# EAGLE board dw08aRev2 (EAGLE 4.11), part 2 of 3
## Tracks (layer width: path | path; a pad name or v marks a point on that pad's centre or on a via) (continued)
I_ACCEPT  (via drill 0.61) (continued)
  Bottom 0.152: v151.38,13.21 154.94,13.21 172.21,30.48 173.61,30.48 184.28,41.15 184.28,42.16 v198.75,56.64 | B07.S2 224.28,21.34 225.93,22.99 225.93,24.38 226.95,25.4 v227.33,25.4 227.71,25.65 227.97,25.91 230.76,25.91 231.52,26.67 v233.93,26.67 | v249.17,11.68 v258.95,21.46 | v232.28,63.25 232.41,63.37 233.55,63.37 235.46,65.28 235.46,65.66 236.6,66.8 236.6,67.06 259.59,90.04 261.24,90.04 A04.S2 | v238.51,56.9 238.51,52.2 228.09,41.78 228.09,41.27 v221.11,34.29
I_ACCLR  (via drill 0.61)
  Top 0.152: v297.94,54.36 297.94,56.13 297.43,56.64 297.05,56.64 296.55,57.15 296.55,57.66 v285.12,69.09 | v292.48,78.11 292.48,80.64 278.38,94.74 276.99,94.74 275.34,96.39 A03.P2 | v124.71,2.41 84.71,42.42 81.66,42.42 B18.J2 | v187.83,15.88 188.98,15.88 191.01,13.84 191.01,13.72 194.69,10.03 v203.58,10.03 | v214,15.88 214.25,15.88 v228.09,2.03 | v242.95,12.7 242.95,12.57 245.49,10.03 247.27,10.03 v250.57,6.73
  Bottom 0.152: v297.94,54.36 250.44,6.86 v250.57,6.73 251.33,5.97 252.22,5.97 256.29,10.03 259.33,10.03 267.21,17.91 267.21,21.21 272.54,26.54 273.94,26.54 B03.P2 | v285.12,69.09 285.12,70.74 v292.48,78.11 | v124.71,2.41 129.92,2.41 131.57,0.76 168.53,0.76 170.31,2.54 171.58,2.54 172.47,3.43 172.72,3.43 173.48,4.19 173.99,4.19 185.17,15.37 187.32,15.37 v187.83,15.88 | v203.58,10.03 204.72,10.03 207.26,12.57 208.41,12.57 208.79,12.95 211.46,12.95 212.22,13.72 212.22,14.1 v214,15.88 | v228.09,2.03 229.49,2.03 230.63,3.17 233.43,3.17 v242.95,12.7
I_ADD00  (via drill 0.61)
  Top 0.152: v62.61,51.31 58.8,55.12 56.26,55.12 B20.D2 | v108.58,92.46 112.27,92.46 115.32,89.41 119.13,89.41 v163.7,44.83 | v197.61,76.2 197.61,76.07 204.09,69.6 204.98,69.6 210.57,64.01 214.63,64.01 v216.41,62.23 | v240.92,59.31 239.78,60.45 239.01,60.45 228.22,71.25 v228.22,71.88 227.97,72.26 v225.04,75.18 | v253.49,71.88 261.37,64.01 262.76,64.01 264.41,62.36 B04.B1 | v272.92,123.06 271.65,124.33 270.89,124.33 265.56,129.67 265.56,131.06 A04.B1
  Bottom 0.152: v62.61,51.31 67.44,51.31 v108.58,92.46 | v163.7,44.83 163.83,44.83 185.17,66.17 185.67,66.17 190.75,71.25 192.66,71.25 v197.61,76.2 | v216.41,62.23 218.57,62.23 v228.22,71.88 | v240.92,59.31 v253.49,71.88 | v272.92,123.06 272.8,123.06 241.3,91.57 240.79,91.57 232.41,83.19 232.41,82.55 v225.04,75.18
I_ADD01  (via drill 0.61)
  Top 0.152: v81.66,27.3 60.2,48.77 56.26,48.77 B20.F2 | v190.5,119.63 192.53,119.63 204.09,108.08 209.04,108.08 228.6,88.52 230,88.52 232.66,85.85 233.17,85.85 235.2,83.82 | 235.2,83.82 261.37,57.66 262.76,57.66 264.41,56.01 B04.D1 | v269.37,118.24 265.56,122.05 265.56,124.71 A04.D1 | 235.2,83.82 v234.95,83.57
  Bottom 0.152: v81.66,27.3 82.8,27.3 89.92,34.42 101.6,34.42 149.99,82.8 150.5,82.8 165.99,98.3 166.5,98.3 169.29,101.09 173.35,101.09 178.69,106.43 178.69,106.68 185.42,113.41 185.42,113.92 186.82,115.32 186.82,115.95 187.96,117.09 188.59,117.09 189.99,118.49 189.99,119.13 v190.5,119.63 | v269.37,118.24 269.37,115.32 265.68,111.63 264.29,111.63 264.03,111.38 262.13,111.38 235.46,84.71 235.46,84.07 v234.95,83.57
I_ADD02  (via drill 0.61)
  Top 0.152: v108.71,80.9 108.84,80.9 116.46,73.28 117.09,73.28 125.73,64.64 126.62,64.64 v139.95,51.31 | v220.09,128.91 220.98,128.91 233.17,116.71 233.17,116.46 v246.63,103 | v266.83,55.37 267.84,54.36 267.84,53.09 B04.E1 | v268.48,60.33 268.48,61.21 260.6,69.09 260.22,69.09 250.44,78.87 249.81,78.87 243.46,85.22 243.21,85.22 v242.32,86.11 | v248.92,105.16 v255.14,98.93
  Bottom 0.152: v108.71,80.9 105.54,77.72 103.38,77.72 102.74,77.09 100.33,77.09 67.18,43.94 61.34,43.94 60.71,43.31 56.26,43.31 B20.J2 | v139.95,51.31 141.86,51.31 155.07,64.52 155.07,67.69 155.19,67.82 155.19,68.33 183.26,96.39 183.64,96.39 188.34,101.09 192.28,101.09 v220.09,128.91 | v246.63,103 246.89,103 249.05,105.16 | 249.05,105.16 264.41,120.52 266.32,120.52 267.59,121.79 A04.E1 | v266.83,55.37 266.83,58.93 267.72,59.82 267.97,59.82 v268.48,60.33 | v255.14,98.93 v242.32,86.11 | 249.05,105.16 v248.92,105.16
I_ADD03  (via drill 0.61)
  Top 0.152: v65.02,29.08 58.04,36.07 56.26,36.07 B20.L2 | v81.28,32.13 81.53,32.13 v91.57,22.1 | v202.82,116.46 202.82,116.2 210.57,108.46 214.38,108.46 220.85,101.98 221.62,101.98 222.38,101.22 222.88,101.22 223.77,100.33 224.54,100.33 239.65,85.22 240.28,85.22 242.32,87.25 | 242.32,87.25 248.67,80.9 249.3,80.9 268.86,61.34 268.86,61.09 269.24,60.71 269.24,59.44 v274.7,53.98 | v266.19,117.6 267.46,116.33 267.59,116.33 A04.H1 | v245.62,97.03 245.62,95.76 v248.16,93.22 | 242.32,87.25 v242.19,87.38
  Bottom 0.152: v65.02,29.08 78.23,29.08 v81.28,32.13 | v91.57,22.1 107.7,22.1 121.28,35.69 121.67,35.69 141.73,55.75 142.11,55.75 v202.82,116.46 | v274.7,53.98 274.57,53.98 270.38,49.78 270.38,48.77 268.35,46.74 B04.H1 | v266.19,117.6 266.19,116.97 254.51,105.28 254,105.28 245.75,97.03 v245.62,97.03 | v248.16,93.22 248.03,93.22 v242.19,87.38
I_ADD04  (via drill 0.61)
  Top 0.152: v126.75,78.74 129.29,78.74 158.24,49.78 158.24,45.85 v159.13,44.96 | v196.85,77.72 200.91,77.72 v213.11,65.53 | v263.65,44.2 264.41,43.43 264.41,43.31 B04.J1 | v266.32,47.5 266.32,49.66 v233.17,82.8
  Bottom 0.152: v126.75,78.74 79.25,31.24 61.34,31.24 60.71,30.61 56.26,30.61 B20.N2 | v159.13,44.96 160.91,44.96 161.42,45.47 162.05,45.47 189.61,73.03 189.61,73.66 193.17,77.22 196.34,77.22 v196.85,77.72 | v213.11,65.53 215.77,65.53 224.66,74.42 225.43,74.42 225.81,74.8 225.81,75.44 v233.17,82.8 234.19,83.82 234.19,83.95 262,111.76 263.91,111.76 264.41,112.27 A04.J1 | v263.65,44.2 263.65,44.83 v266.32,47.5
I_ADD05  (via drill 0.61)
  Top 0.152: v106.93,21.34 107.19,21.34 v123.83,4.7 | v170.56,34.42 175.77,34.42 v198.37,11.81 | v202.06,15.49 202.06,14.86 208.03,8.89 208.79,8.89 v215.52,2.16 | v237.87,15.49 v234.95,15.49 | v262.89,38.23 263.14,38.23 264.41,36.96 B04.L1 | v264.03,109.09 264.67,108.46 264.67,107.06 A04.L1 | v275.08,120.52 274.45,120.52 272.67,122.3 272.42,122.3 v258.19,136.53 | v256.16,136.53 253.37,139.32 248.41,139.32 v247.9,139.83 | v147.07,43.81 147.7,43.81 v162.94,28.57
  Bottom 0.152: v106.93,21.34 104.14,18.54 99.44,18.54 90.55,9.65 58.8,9.65 57.02,7.87 54.48,10.41 54.48,11.68 58.8,16 56.01,18.8 56.01,23.11 B20.R2 | v123.83,4.7 136.4,4.7 159.77,28.07 162.94,28.07 | 162.94,28.07 164.21,28.07 v170.56,34.42 | v202.06,15.49 v198.37,11.81 | v215.52,2.16 216.66,3.3 217.04,3.3 226.31,12.57 229.36,12.57 229.74,12.95 232.41,12.95 v234.95,15.49 | v237.87,15.49 240.16,15.49 v262.89,38.23 | v264.03,109.09 264.03,109.47 v275.08,120.52 | v256.16,136.53 v258.19,136.53 | v247.9,139.83 246.89,138.81 246.25,138.81 245.36,137.92 242.32,137.92 238.89,134.49 238.25,134.49 219.71,115.95 219.2,115.95 167.26,64.01 167,64.01 166.5,63.5 166.5,63.25 v147.07,43.81 | 162.94,28.07 v162.94,28.57
I_ADD06  (via drill 0.61)
  Top 0.152: v145.92,143.26 176.15,143.26 v178.82,140.59 | v195.07,142.88 211.46,142.88 212.34,141.99 213.23,141.99 v221.36,133.86 | v226.31,133.86 229.11,133.86 v233.93,129.03 | v252.09,142.88 252.09,142.24 257.3,137.03 257.3,136.27 257.81,135.76 258.44,135.76 272.29,121.92 272.54,121.92 v279.53,114.94 | v271.14,32.89 268.99,32.89 B04.M1 | v276.1,37.85 276.1,41.15 v273.56,43.69 | v295.91,70.1 295.91,70.61 287.78,78.74 287.78,79.38 280.67,86.49 280.67,87.63 275.21,93.09 275.21,94.61 270.38,99.44 270.38,100.84 268.73,102.49 A04.M1
  Bottom 0.152: v145.92,143.26 69.72,67.06 68.58,67.06 68.33,66.8 64.39,66.8 63.75,66.17 58.17,66.17 52.45,60.45 51.69,60.45 49.78,58.55 48.51,58.55 45.97,56.01 43.56,56.01 B21.D2 | v178.82,140.59 189.99,140.59 191.39,139.19 v195.07,142.88 | v221.36,133.86 v226.31,133.86 | v233.93,129.03 235.33,129.03 242.32,136.02 245.24,136.02 v252.09,142.88 | v279.53,114.94 279.53,112.78 272.03,105.28 270.64,105.28 268.99,103.63 A04.M1 | v276.1,37.85 v271.14,32.89 | v273.56,43.69 273.56,47.24 291.59,65.28 291.59,65.79 v295.91,70.1
I_ADD07  (via drill 0.61)
  Top 0.152: v266.83,28.32 267.59,27.56 267.59,27.43 B04.P1 | v273.3,36.2 273.3,37.59 v270.51,40.39 270.13,40.64 263.27,47.5 v259.59,47.5 | v291.97,67.31 291.97,69.34 282.45,78.87 282.45,80.52 279.53,83.44 279.53,83.95 276.73,86.74 276.73,87.25 275.08,88.9 274.57,88.9 270.38,93.09 270.38,94.49 268.73,96.14 A04.P1 | v129.92,120.52 133.86,120.52 147.19,107.19 148.34,107.19 150.24,105.28 155.83,105.28 188.47,72.64 193.8,72.64 v198.12,68.33 | v208.41,77.85 212.72,77.85 237.62,52.96 237.62,49.91 v237.74,49.78 | v235.59,43.43 235.59,42.29 237.62,40.26 237.62,39.62 238,39.24 240.03,39.24 v243.97,35.31
  Bottom 0.152: v266.83,28.32 266.83,29.72 v273.3,36.2 | v270.51,40.39 270.64,40.39 272.54,42.29 272.54,46.74 291.21,65.41 291.21,66.55 v291.97,67.31 | v129.92,120.52 100.97,91.57 96.27,91.57 64.52,59.82 58.17,59.82 55.63,57.28 54.86,57.28 53.98,56.39 52.07,56.39 45.34,49.66 43.56,49.66 B21.F2 | v198.12,68.33 199.52,68.33 201.55,70.36 201.55,70.99 v208.41,77.85 | v237.74,49.78 237.74,45.59 v235.59,43.43 | v243.97,35.31 247.4,35.31 v259.59,47.5
I_ADD08  (via drill 0.61)
  Top 0.152: v301.37,55.5 301.37,55.75 295.78,61.34 295.78,64.39 295.4,64.77 295.4,65.91 v295.02,66.29 | v299.85,72.64 299.85,74.3 293.5,80.64 293.5,81.28 v280.8,93.98 | v274.7,88.14 274.19,88.14 273.3,89.03 270,89.03 268.99,90.04 A04.S1 | v41.78,28.57 45.21,25.15 46.23,25.15 48.64,22.73 60.83,22.73 73.91,9.65 98.17,9.65 v102.74,5.08 | v163.07,14.35 164.97,14.35 169.29,10.03 172.47,10.03 179.71,2.79 v179.71,2.67 | v216.15,29.46 216.15,26.67 226.44,16.38 231.39,16.38 v243.46,4.32 | v260.35,20.32 260.6,20.32 264.54,16.38 265.68,16.38 268.61,19.3 267.97,19.94 B04.S1
  Bottom 0.152: v301.37,55.5 301.12,55.24 301.12,51.82 283.72,34.42 280.42,34.42 278.89,32.89 278.89,29.59 270.89,21.59 270.51,21.59 270,21.08 268.99,21.08 B04.S1 | v295.02,66.29 295.02,67.82 v299.85,72.64 | v280.8,93.98 280.54,93.98 v274.7,88.14 | v41.78,28.57 41.78,37.08 42.42,37.72 42.42,42.16 B21.J2 | v102.74,5.08 107.06,0.76 119.25,0.76 122.43,3.94 149.99,3.94 151,4.95 153.67,4.95 v163.07,14.35 | v179.71,2.67 188.47,2.67 196.34,10.54 196.34,10.92 197.99,12.57 198.37,12.57 199.52,13.72 199.52,14.1 201.68,16.26 203.07,16.26 213.49,26.67 213.49,26.8 v216.15,29.46 | v243.46,4.32 250.32,11.18 250.32,11.68 258.95,20.32 v260.35,20.32
I_ADD09  (via drill 0.61)
  Top 0.152: v157.23,140.84 v169.29,140.84 | v178.18,142.37 179.45,143.64 233.81,143.64 235.2,142.24 235.59,142.24 236.35,141.48 236.73,141.48 242.19,136.02 243.46,136.02 250.32,129.16 250.32,128.52 v251.84,127 | v281.69,77.09 283.08,77.09 v283.59,76.58 | v298.96,91.69 298.96,94.87 296.67,97.16 296.67,97.92 286.38,108.2 283.97,108.2 265.68,126.49 262.51,126.49 v262.38,126.62
  Bottom 0.152: v157.23,140.84 142.88,126.49 137.54,126.49 135.25,124.21 134.75,124.21 100.2,89.66 99.06,89.66 91.06,81.66 91.06,79.76 77.47,66.17 77.22,66.17 71.63,60.58 68.58,60.58 48.77,40.77 45.47,40.77 43.31,38.61 43.31,37.21 B21.L2 | v169.29,140.84 176.66,140.84 v178.18,142.37 | v251.84,127 256.92,127 258.06,125.86 A04.D2 259.46,125.86 260.22,126.62 v262.38,126.62 | v281.69,77.09 269.75,65.15 269.75,64.39 268.99,63.63 268.99,62.99 262,56.01 259.46,56.01 B04.D2 | v283.59,76.58 284.23,76.58 286.38,78.74 286.38,79.12 v298.96,91.69
I_ADD10  (via drill 0.61)
  Top 0.152: v101.22,7.75 98.93,10.03 74.04,10.03 59.05,25.02 48.51,25.02 48.01,25.53 45.34,25.53 43.31,27.56 43.31,29.46 B21.N2 | v142.49,38.1 144.53,38.1 v147.32,35.31 | v188.85,73.41 194.18,73.41 v196.22,71.37 | v204.6,76.33 216.92,64.01 221.23,64.01 231.78,53.47 232.03,53.47 v241.68,43.81 | v256.67,56.9 256.67,56.01 258.19,54.48 259.59,54.48 261.24,52.83 B04.E2 | v258.7,115.95 258.7,115.57 v272.54,101.73 | v260.99,86.87 260.99,86.74 266.19,81.53 266.19,79.88 v278,68.07
  Bottom 0.152: v101.22,7.75 106.43,7.75 107.06,8.38 107.82,8.38 118.36,18.92 123.32,18.92 v142.49,38.1 | v147.32,35.31 147.96,35.31 159.77,47.12 163.07,47.12 180.47,64.52 180.47,65.02 v188.85,73.41 | v196.22,71.37 198.37,71.37 198.75,71.75 200.03,71.75 v204.6,76.33 | v241.68,43.81 242.32,43.81 251.33,52.83 252.6,52.83 v256.67,56.9 | v258.7,115.95 261.49,118.75 261.49,121.54 A04.E2 | v272.54,101.73 272.54,97.79 262,87.25 261.37,87.25 v260.99,86.87 | v278,68.07 278,66.8 275.21,64.01 274.95,64.01 274.57,63.63 274.57,61.85 267.33,54.61 265.81,54.61 265.68,54.48 264.29,54.48 262.64,52.83 B04.E2
I_ADD11  (via drill 0.61)
  Top 0.152: v170.94,97.92 175.64,97.92 v184.15,89.41 | v239.01,141.1 239.9,141.1 254.76,126.24 254.76,124.71 259.84,119.63 259.84,118.24 261.49,116.59 A04.H2 | v222.76,50.04 v242.7,30.1 | v223.14,63.25 v228.98,57.4 | v219.07,61.59 218.19,61.59 213.49,66.29 212.85,66.29 200.53,78.61 198.12,78.61 197.74,78.99 192.53,78.99 189.48,82.04 185.04,82.04 v181.99,85.09
  Bottom 0.152: v170.94,97.92 166.12,97.92 150.62,82.42 150.11,82.42 92.58,24.89 80.39,24.89 72.64,17.14 71.25,18.54 61.34,18.54 60.2,17.4 57.66,19.94 57.66,21.21 58.8,22.35 56.26,24.89 48.64,24.89 48.01,24.26 43.56,24.26 B21.R2 | v184.15,89.41 186.31,89.41 | 186.31,89.41 191.77,94.87 193.8,94.87 202.18,103.25 202.18,103.89 204.09,105.79 204.09,106.17 220.47,122.56 220.6,122.56 239.01,140.97 v239.01,141.1 | v242.7,30.1 258.19,45.59 261.24,45.59 B04.H2 | v222.76,50.04 223.14,50.04 228.09,54.99 228.09,56.52 v228.98,57.4 | v223.14,63.25 220.34,63.25 219.58,62.48 219.58,62.1 v219.07,61.59 | 186.31,89.41 v181.99,85.09
I_BAC00  (via drill 0.61)
  Top 0.152: v195.83,34.29 186.18,43.94 186.18,45.34 B10.H2 | v224.41,63.25 225.43,63.25 226.31,62.36 B07.B1 | v275.97,93.47 281.05,88.39 281.05,86.61 v288.54,79.12 302.77,64.9 302.77,62.61 B01.B1 | v305.82,117.47 305.82,121.16 305.31,121.67 305.31,129.41 303.66,131.06 A01.B1 | v254.76,87.88 259.08,83.57 260.22,83.57 v276.23,67.56
  Bottom 0.152: v195.83,34.29 195.83,34.67 v224.41,63.25 | v275.97,93.47 275.97,93.98 283.46,101.47 283.97,101.47 286.77,104.27 291.08,104.27 294.39,107.57 295.91,107.57 v305.82,117.47 | v254.76,87.88 249.3,82.42 248.67,82.42 247.14,80.9 247.14,80.39 229.11,62.36 227.71,62.36 B07.B1 | v276.23,67.56 276.35,67.56 277.62,68.83 278.26,68.83 v288.54,79.12
I_BAC01  (via drill 0.61)
  Top 0.152: v185.42,30.23 186.18,30.23 v192.02,24.38 | v224.79,57.28 225.04,57.28 226.31,56.01 B07.D1 | v301.75,60.07 302.77,59.05 302.77,56.26 B01.D1 | v301.75,64.01 301.75,65.02 300.61,66.17 298.58,66.17 v285.62,79.12 285.24,79.38 v283.59,79.38 | v306.2,101.6 306.2,101.73 305.31,102.62 305.31,114.55 304.67,115.19 304.67,115.82 302.13,118.36 302.13,119.63 304.93,122.43 304.93,123.44 303.66,124.71 A01.D1 | v249.05,81.66 266.06,64.64 267.08,64.64 v268.22,63.5
  Bottom 0.152: v185.42,30.23 183.26,30.23 B10.N2 | v192.02,24.38 224.79,57.15 v224.79,57.28 225.04,57.66 v249.05,81.66 | v301.75,64.01 v301.75,60.07 | v285.62,79.12 285.88,79.12 294.13,87.38 294.13,88.01 300.99,94.87 300.99,95.5 303.15,97.66 303.4,97.66 305.82,100.08 305.82,101.22 v306.2,101.6 | v268.22,63.5 268.35,63.5 269.37,64.52 269.37,65.91 281.31,77.85 282.07,77.85 v283.59,79.38
I_BAC02  (via drill 0.61)
  Top 0.152: v184.28,16.64 185.29,15.62 185.29,14.99 B10.U2 | v222.25,55.75 223.39,55.75 v228.22,50.93 | v278.13,15.37 275.21,15.37 272.03,18.54 271.53,18.54 271.02,19.05 271.02,19.56 259.33,31.24 255.4,31.24 242.06,44.58 241.81,44.58 v232.16,54.23
  Bottom 0.152: v184.28,16.64 184.28,16.89 187.2,19.81 187.2,20.45 189.99,23.24 189.99,23.5 191.64,25.15 192.28,25.15 214.25,47.12 214.25,47.5 221.74,54.99 221.74,55.24 v222.25,55.75 | v228.22,50.93 228.47,50.93 229.49,51.94 B07.E1 232.03,54.23 v232.16,54.23 232.54,54.48 233.93,54.48 236.73,57.28 237.24,57.28 266.95,87 266.95,87.76 268.61,89.41 268.86,89.41 272.8,93.34 272.8,93.6 274.95,95.76 275.21,95.76 276.23,96.77 276.61,96.77 296.55,116.71 296.55,117.35 297.18,117.98 297.43,117.98 301.24,121.79 305.69,121.79 A01.E1 | v278.13,15.37 302.13,39.37 302.13,43.43 304.17,45.47 304.17,46.86 305.05,47.75 305.05,48.39 305.82,49.15 305.82,50.93 305.94,51.05 305.94,51.69 B01.E1
I_BAC03  (via drill 0.61)
  Top 0.152: v177.8,49.53 178.31,49.53 v206.63,21.21 | v222.63,36.96 v222.63,34.67 222.76,34.29 222.76,31.11 228.09,25.78 228.09,25.53 230.38,23.24 230.38,22.99 v235.59,17.78 | v296.16,65.15 299.72,61.59 299.72,60.96 302.13,58.55 302.13,54.99 v303.53,53.59 304.67,52.45 304.67,51.94 305.82,50.8 305.82,50.16 306.58,49.4 306.58,46.74 B01.H1 | v304.67,77.6 304.42,77.6 301.75,80.26 301.75,80.52 293.75,88.52 292.74,88.52 v289.05,92.2 | v244.35,24.51 244.35,23.88 245.49,22.73 249.43,22.73 253.24,18.92 255.52,18.92 v260.22,14.22 | v282.07,35.18 v283.59,33.66
  Bottom 0.152: v177.8,49.53 177.29,49.02 177.29,48.64 175.13,46.48 173.74,46.48 B11.H2 | v206.63,21.21 207.01,21.21 215.39,29.59 215.39,30.99 216.41,32 219.96,32 v222.63,34.67 | v222.63,36.96 222.76,36.96 228.09,42.29 228.09,43.69 229.74,45.34 B07.H1 | v296.16,65.15 301.75,70.74 301.75,74.68 v304.67,77.6 | v289.05,92.2 289.05,96.14 295.4,102.49 295.4,103.25 304.29,112.14 304.29,113.54 305.94,115.19 A01.H1 | v235.59,17.78 237.62,17.78 v244.35,24.51 | v260.22,14.22 260.22,14.73 280.29,34.8 281.69,34.8 v282.07,35.18 | v283.59,33.66 v303.53,53.59
I_BAC04  (via drill 0.61)
  Top 0.152: v186.82,16.89 173.74,29.97 170.56,29.97 B11.N2 | v205.1,35.69 206.5,35.69 v212.47,29.72 | v305.82,48.01 305.82,49.02 v297.31,57.53 | v300.48,61.34 300.48,61.98 295.4,67.06 294.77,67.06 282.83,78.99 282.83,80.64 279.91,83.57 279.91,87.25 v279.65,87.5 | v228.85,41.4 227.84,42.42 227.71,42.42 B07.J1 | v270.38,83.57 270.51,83.57 v273.05,81.03
  Bottom 0.152: v186.82,16.89 186.82,17.53 193.17,23.88 193.17,24.51 199.26,30.61 200.03,30.61 v205.1,35.69 | v212.47,29.72 212.47,29.97 223.27,40.77 224.66,40.77 226.31,42.42 B07.J1 | v305.82,48.01 304.55,46.74 304.55,45.34 303.66,44.45 303.66,43.56 B01.J1 | v297.31,57.53 297.31,58.17 v300.48,61.34 | A01.J1 302.51,112.27 300.86,110.62 299.47,110.62 295.53,106.68 295.53,106.43 293.37,104.27 293.12,104.27 279.65,90.81 v279.65,87.5 279.4,87.12 273.3,81.03 v273.05,81.03 | v228.85,41.4 228.85,42.04 237.36,50.55 238,50.55 261.37,73.91 261.37,74.55 v270.38,83.57
I_BAC05  (via drill 0.61)
  Top 0.152: v205.87,55.12 206.76,55.12 210.57,51.31 213.87,51.31 215.39,49.78 215.39,46.48 216.92,44.96 217.17,44.96 217.93,44.2 217.93,43.43 219.96,41.4 220.47,41.4 v224.92,36.96 | v280.04,16.13 277.5,16.13 276.73,16.89 276.73,21.97 260.22,38.48 259.08,38.48 v251.46,46.1 | v236.47,30.48 235.2,30.48 233.93,31.75 233.43,31.75 230.76,34.42 229.36,34.42 227.71,36.07 B07.L1 | v299.59,104.78 300.1,104.78 304.29,100.58 304.29,100.08 304.67,99.69 304.93,99.69 v306.2,98.42 | v289.81,73.79 290.32,73.79 291.97,72.14 291.97,71.5 302.64,60.83 303.28,60.83 304.67,59.44 304.67,52.96 305.05,52.58 305.05,52.07 v306.58,50.55
  Bottom 0.152: v205.87,55.12 186.82,36.07 186.82,32.77 186.18,32.13 186.18,29.84 173.48,17.14 173.48,14.99 B11.U2 | v224.92,36.96 226.31,36.96 B07.L1 | v280.04,16.13 299.97,36.07 302.51,36.07 B01.L1 303.66,37.21 305.31,38.86 305.31,46.61 305.94,47.24 306.2,47.24 306.58,47.62 v306.58,50.55 | v251.46,46.1 251.46,45.47 v236.47,30.48 | v299.59,104.78 300.74,105.92 302.51,105.92 A01.L1 | v306.2,98.42 306.2,98.3 302.13,94.23 302.13,91.31 301.88,91.06 301.88,90.42 297.05,85.6 297.05,83.31 296.67,82.93 296.67,82.42 295.78,81.53 295.78,79.76 v289.81,73.79
I_BAC06  (via drill 0.61)
  Top 0.152: 237.24,27.94 240.79,24.38 240.79,21.59 241.55,20.83 241.55,20.32 245.49,16.38 250.32,16.38 255.52,11.18 257.05,11.18 258.19,10.03 259.59,10.03 v264.29,5.33 | 237.24,27.94 233.81,31.37 233.3,31.37 231.78,32.89 230.89,32.89 B07.M1 | v189.99,71.63 193.68,71.63 197.74,67.56 200.03,67.56 202.82,64.77 203.07,64.77 207.39,60.45 207.39,59.94 222.63,44.7 222.63,44.45 229.74,37.34 230.38,37.34 233.3,34.42 233.68,34.42 237.24,30.86 237.24,27.94 | v162.05,44.32 B12.H2 | v280.8,73.79 280.8,69.72 302.51,48.01 302.51,45.21 304.29,43.43 304.29,35.69 305.94,34.04 B01.M1
  Bottom 0.152: v264.29,5.33 292.74,5.33 297.94,10.54 297.94,16.89 301.12,20.07 301.12,25.91 304.8,29.59 304.8,31.5 305.94,32.64 B01.M1 | v162.05,44.32 163.32,45.59 163.96,45.59 v189.99,71.63 | v280.8,73.79 282.83,75.82 282.83,76.96 284.86,78.99 284.86,79.5 286.13,80.77 284.99,81.92 284.99,84.07 297.31,96.39 297.94,96.39 304.29,102.74 305.69,102.74 A01.M1
I_BAC07  (via drill 0.61)
  Top 0.152: v263.65,4.19 261.75,6.1 256.29,6.1 255.91,6.48 252.73,6.48 236.98,22.23 236.98,22.61 234.06,25.53 233.3,25.53 232.28,26.54 230.89,26.54 B07.P1 229.74,27.69 228.09,29.34 228.09,30.73 227.58,31.24 v225.81,31.24 | v186.18,8.76 185.29,9.65 181.86,9.65 179.96,11.56 179.58,11.56 170.43,20.7 169.16,20.7 161.16,28.7 160.4,28.7 159.38,29.72 157.86,29.72 B12.N2 | v211.84,17.4 v205.49,23.75 | v304.42,84.96 v304.42,94.87 | v303.66,59.31 v291.21,71.75 | v292.23,47.5 292.23,42.8 304.29,30.73 304.29,29.34 305.94,27.69 B01.P1
  Bottom 0.152: v263.65,4.19 292.1,4.19 298.32,10.41 298.32,16.76 301.5,19.94 301.5,20.45 304.29,23.24 304.29,24.64 305.94,26.29 B01.P1 | v186.18,8.76 190.5,8.76 v205.49,23.75 | v211.84,17.4 211.96,17.4 v225.81,31.24 | v291.21,71.75 v304.42,84.96 | v303.66,59.31 303.66,58.93 v292.23,47.5 | v304.42,94.87 A01.P1
I_BAC08  (via drill 0.61)
  Top 0.152: v175.26,4.32 174.75,4.83 170.94,4.83 165.74,10.03 162.94,10.03 160.78,12.19 160.78,13.59 B12.U2 | v194.56,20.7 199.9,15.37 200.53,15.37 208.66,7.24 208.66,6.6 v209.3,5.97 | v227.71,22.1 228.47,22.1 229.49,21.08 B07.S1 | v232.16,22.35 248.28,6.22 248.54,6.22 249.81,4.95 257.94,4.95 260.6,2.29 262.76,2.29 263.02,2.03 266.7,5.71 266.7,7.75 266.57,7.87 270.89,12.19 278.51,12.19 289.05,1.65 305.94,18.54 305.94,19.94 B01.S1 305.94,21.34 304.29,22.99 304.29,24.38 296.55,32.13 v296.55,34.92 | v293.62,75.31 293.62,74.55 v305.44,62.74
  Bottom 0.152: v175.26,4.32 178.18,4.32 v194.56,20.7 | v209.3,5.97 211.58,5.97 v227.71,22.1 | v232.16,22.35 230.89,21.08 B07.S1 | v293.62,75.31 305.94,87.63 305.94,89.79 A01.S1 | v305.44,62.74 305.44,59.44 305.31,59.31 305.31,49.15 304.67,48.51 304.67,47.88 303.78,46.99 303.78,45.59 301.75,43.56 301.75,39.75 297.43,35.43 297.05,35.43 v296.55,34.92
I_BAC09  (via drill 0.61)
  Top 0.152: v219.07,56.77 219.2,56.77 219.96,56.01 B07.D2 | B13.H2 148.34,45.59 152.27,45.59 157.23,40.64 157.73,40.64 172.47,25.91 176.15,25.91 v184.15,17.91 199.9,2.16 v200.28,2.16 | v248.16,5.46 244.73,8.89 240.28,8.89 232.28,16.89 232.28,20.19 v229.62,22.86 | v236.22,72.14 235.08,72.14 v233.93,73.28
  Bottom 0.152: v184.15,17.91 184.66,17.91 186.82,20.07 186.82,23.37 187.32,23.88 187.32,24.38 193.04,30.1 193.04,30.35 196.6,33.91 196.6,34.29 v219.07,56.77 219.46,57.02 227.33,64.9 227.33,66.42 232.79,71.88 232.79,72.14 v233.93,73.28 | v248.16,5.46 252.73,10.03 252.98,10.03 296.42,53.47 296.42,54.86 B01.D2 | v229.62,22.86 228.09,21.34 227.46,21.34 211.58,5.46 210.19,5.46 209.8,5.08 208.41,5.08 208.15,4.83 202.95,4.83 v200.28,2.16 | v236.22,72.14 244.98,80.9 244.98,81.53 249.68,86.23 249.68,86.87 258.19,95.38 258.19,98.04 259.08,98.93 259.33,98.93 288.29,127.89 289.69,127.89 291.72,125.86 296.16,125.86 A01.D2
I_BAC10  (via drill 0.61)
  Top 0.152: v193.55,76.33 196.34,76.33 197.23,75.44 197.74,75.44 203.96,69.22 204.85,69.22 210.44,63.63 210.95,63.63 220.09,54.48 221.49,54.48 223.14,52.83 B07.E2 224.28,51.69 225.93,50.04 225.93,48.64 249.81,24.77 v250.57,24.77 | v288.16,42.16 287.78,42.16 v284.99,44.96 | v274.83,41.27 274.7,41.27 v271.53,44.45 | v300.61,119.25 300.48,119.38 300.48,121.54 A01.E2 | v262,80.52 262,79.88 277.75,64.14 277.75,63.63 278.89,62.48 278.89,59.18 283.59,54.48 283.85,54.48 v284.35,53.98 | v279.4,48.01 279.78,48.01 280.29,47.5 281.18,47.5 v283.34,45.34
  Bottom 0.152: v193.55,76.33 162.31,45.09 161.67,45.09 150.62,34.04 149.99,34.04 147.45,31.5 146.94,31.5 146.05,30.61 145.16,30.61 B13.N2 | v288.16,42.16 297.94,51.94 299.34,51.94 B01.E2 | 283.34,44.96 282.07,44.96 281.69,44.58 281.18,44.58 278.38,41.78 275.34,41.78 v274.83,41.27 | 283.34,44.96 v284.99,44.96 | v271.53,44.45 270.26,44.45 v250.57,24.77 | v300.61,119.25 300.61,119.13 275.72,94.23 275.59,94.23 274.32,92.96 274.32,92.84 v262,80.52 | v284.35,53.98 284.35,52.96 280.42,49.02 280.29,49.02 279.4,48.13 v279.4,48.01 | 283.34,44.96 v283.34,45.34
I_BAC11  (via drill 0.61)
  Top 0.152: v292.61,51.18 297.31,46.48 299.34,46.48 B01.H2 | v303.02,66.42 303.02,67.69 302.13,68.58 302.13,68.83 300.23,70.74 300.23,71.12 299.08,72.26 299.08,74.55 276.23,97.41 v276.23,97.54 | v296.8,120.65 296.93,120.65 297.94,119.63 297.94,118.24 299.59,116.59 A01.H2 | v145.03,19.05 147.19,16.89 147.19,14.99 B13.U2 | v176.15,50.8 182.63,50.8 v194.69,38.73 | v215.9,55.88 215.9,55.63 221.74,49.78 221.74,48.39 223.39,46.74 B07.H2 224.28,45.34 225.93,43.69 225.93,42.29 228.35,39.88 v228.6,39.88 | v272.67,20.32 272.54,20.32 271.27,21.59 269.62,21.59 v247.78,43.43 | v235.46,34.8 233.43,34.8 v230.12,38.1
  Bottom 0.152: v292.61,51.18 292.61,55.24 293.75,56.39 293.75,57.15 v303.02,66.42 | v276.23,97.54 276.23,101.85 284.48,110.11 284.48,110.87 285.62,112.01 285.62,112.52 290.58,117.47 293.62,117.47 v296.8,120.65 | v145.03,19.05 145.03,19.68 v176.15,50.8 | v194.69,38.73 195.83,38.73 197.87,40.77 201.17,40.77 215.39,54.99 215.39,55.37 v215.9,55.88 | v272.67,20.32 297.94,45.59 299.34,45.59 B01.H2 | v247.78,43.43 247.78,42.93 246.63,41.78 242.44,41.78 v235.46,34.8 | v230.12,38.1 228.47,39.75 v228.6,39.88
I_BREAK  (via drill 0.61)
  Top 0.152: v238.25,28.07 238.51,28.07 243.97,22.61 243.97,22.1 v248.54,17.53 | v259.21,28.07 260.6,28.07 261.24,27.43 B04.P2 | v263.14,95.12 262.38,95.89 262.38,96.14 A04.P2 | v233.17,64.14 233.81,64.14 v245.62,52.32 | B23.V2 18.16,10.67 22.61,10.67 23.24,10.03 28.83,10.03 29.46,10.67 B22.V2 | v122.94,23.88 132.08,14.73 134.24,14.73 B14.U2 | v205.99,7.49 205.23,7.49 204.09,8.64 197.49,8.64 195.71,6.86 186.06,16.51 186.06,17.14 176.91,26.29 175.39,26.29 v172.47,29.21 | v146.05,10.03 142.62,10.03 v137.16,15.49
  Bottom 0.152: 220.98,21.72 219.58,23.11 219.58,24.38 221.74,26.54 223.14,26.54 B07.P2 224.54,27.43 226.19,29.08 227.58,29.08 232.28,33.78 232.28,37.08 241.43,46.23 241.43,46.74 243.71,49.02 243.71,50.16 245.62,52.07 v245.62,52.32 | 220.98,21.72 221.87,22.61 223.39,22.61 226.95,26.16 227.71,26.16 229.62,28.07 v238.25,28.07 | v248.54,17.53 248.67,17.53 v259.21,28.07 | v263.14,95.12 263.14,94.11 v233.17,64.14 | v122.94,23.88 120.78,23.88 106.93,10.03 91.44,10.03 90.68,9.27 58.93,9.27 57.15,7.49 34.04,7.49 30.86,10.67 B22.V2 | 220.98,21.72 214.38,15.11 214.12,15.11 211.58,12.57 211.07,12.57 v205.99,7.49 | v172.47,29.21 171.45,29.21 155.07,12.83 152.15,12.83 151.76,12.45 148.46,12.45 v146.05,10.03 | v137.16,15.49 136.4,15.49 135.64,14.73 B14.U2
I_BRKRQ  (via drill 0.61)
  Top 0.152: v79.63,33.4 80.52,32.51 80.52,30.86 B18.N2 | v184.02,137.16 193.29,137.16 219.46,111 219.46,110.74 220.34,109.86 220.98,109.86 v241.43,89.41 | v259.84,37.72 259.21,37.72 256.16,40.77 253.37,40.77 252.98,41.15 251.97,41.15 243.71,49.4 243.71,50.29 v243.21,50.8 | v264.03,74.93 264.03,76.33 260.86,79.5 260.86,80.64 254,87.5 254,89.28 251.08,92.2 250.44,92.2 v248.16,94.49
  Bottom 0.152: v79.63,33.4 79.76,33.4 126.11,79.76 126.62,79.76 v184.02,137.16 | v241.43,89.41 243.46,89.41 247.14,93.09 247.14,93.34 248.28,94.49 | 248.28,94.49 249.56,95.76 249.81,95.76 256.67,102.62 256.67,102.87 257.05,103.25 257.3,103.25 259.84,105.79 259.84,107.19 261.49,108.84 A04.K2 | v259.84,37.72 261.24,39.12 261.37,39.12 B04.K2 | v243.21,50.8 243.21,51.05 243.97,51.82 243.97,55.12 257.81,68.96 258.06,68.96 v264.03,74.93 | v248.16,94.49 248.28,94.49
I_CAINCR  (via drill 0.61)
  Top 0.152: v224.54,55.75 242.44,37.85 243.08,37.85 247.14,33.78 248.54,33.78 B05.M2 | v256.03,88.9 255.52,88.9 251.33,93.09 251.33,93.73 v250.06,95 | v257.43,102.49 257.43,103 v254,106.43 | v107.57,7.24 76.2,38.61 70.87,38.61 68.71,40.77 68.71,42.16 B19.J2 | v120.52,14.22 120.65,14.22 124.84,10.03 127.25,10.03 134.24,3.05 146.69,3.05 151,7.37 153.16,7.37 155.07,5.46 161.67,5.46 v162.81,4.32
  Bottom 0.152: v256.03,88.9 255.52,88.39 255.52,87.5 249.81,81.79 249.81,81.28 233.43,64.9 232.79,64.9 225.55,57.66 225.55,56.9 224.54,55.88 v224.54,55.75 224.16,56.01 192.79,24.64 192.79,24 172.59,3.81 166.62,3.81 164.97,2.16 v162.81,4.32 | v250.06,95 250.06,95.12 v257.43,102.49 | v254,106.43 254,106.3 252.98,105.28 251.59,105.28 249.94,103.63 A05.M2 | v107.57,7.24 113.54,7.24 v120.52,14.22
I_DATA00  (via drill 0.61)
  Top 0.152: v107.95,129.67 137.67,129.67 141.22,126.11 141.48,126.11 v164.72,102.87 | v210.06,137.29 210.57,137.29 v224.03,123.83 | v235.08,132.97 235.71,132.97 v242.32,126.36 | v250.57,60.58 248.92,60.58 v247.9,61.59 | v246.13,60.33 246,60.33 234.31,72.01 234.31,72.14 233.93,72.52 232.92,72.52 231.9,73.53 231.39,73.53 222.63,82.3 222.63,82.55 v202.69,102.49
  Bottom 0.152: v107.95,129.67 33.91,55.63 30.86,55.63 B22.D2 | v164.72,102.87 169.29,107.44 173.86,107.44 180.09,113.67 180.85,113.67 204.47,137.29 v210.06,137.29 | v235.08,132.97 234.95,132.84 232.79,132.84 224.03,124.08 v224.03,123.83 223.65,123.7 218.44,118.49 218.44,118.24 217.17,116.97 216.92,116.97 202.69,102.74 v202.69,102.49 | v242.32,126.36 245.36,126.36 248.67,129.67 250.06,129.67 251.71,131.32 A05.B1 | v250.57,60.58 251.46,61.47 251.71,61.47 B05.B1 | v247.9,61.59 247.4,61.59 v246.13,60.33
I_DATA01  (via drill 0.61)
  Top 0.152: v124.46,133.6 153.16,133.6 162.81,123.95 165.61,123.95 165.86,123.7 167,123.7 167.26,123.44 170.18,123.44 v199.26,94.36 213.74,79.88 216.79,79.88 v224.28,72.39 | v231.9,77.22 232.41,77.22 247.14,62.48 247.14,59.18 248.67,57.66 250.06,57.66 251.71,56.01 B05.D1 | v238.51,135.25 v249.3,124.46 | v222.25,117.35 v222.25,119.63
  Bottom 0.152: v124.46,133.6 105.03,114.17 92.96,114.17 30.61,51.82 30.61,49.91 B22.F2 | v224.28,72.39 227.08,72.39 v231.9,77.22 | v249.3,124.46 249.81,124.97 251.71,124.97 A05.D1 | v238.51,135.25 224.41,121.16 223.77,121.16 v222.25,119.63 | v199.26,94.36 v222.25,117.35
I_DATA02  (via drill 0.61)
  Top 0.152: v49.28,27.3 34.16,42.42 30.86,42.42 B22.J2 | v128.52,98.42 137.03,98.42 v157.86,77.6 | v220.22,136.14 220.98,136.14 226.44,130.68 231.14,130.68 233.55,128.27 234.57,128.27 v246,116.84 | v266.45,65.41 266.32,65.41 249.81,81.92 249.81,82.04 249.43,82.42 248.28,82.42 242.57,88.14 241.81,88.14 240.79,87.12 240.79,86.61 239.78,85.6 232.28,93.09 232.28,97.41 v229.74,99.95
  Bottom 0.152: v49.28,27.3 51.05,27.3 100.46,76.71 102.87,76.71 103.5,77.34 105.66,77.34 106.05,77.72 107.82,77.72 v128.52,98.42 | v157.86,77.6 158.5,77.6 216.92,136.02 220.09,136.02 v220.22,136.14 | 246.76,116.84 248.54,116.84 251.84,120.14 253.24,120.14 254.89,121.79 A05.E1 | 246.76,116.84 v246,116.84 | v266.45,65.41 263.4,62.36 263.4,61.47 261.75,59.82 261.37,59.82 256.03,54.48 256.03,53.09 B05.E1 | v229.74,99.95 229.87,99.95 246.76,116.84
I_DATA03  (via drill 0.61)
  Top 0.152: v78.99,21.97 78.61,22.35 73.91,22.35 73.53,22.73 67.69,22.73 65.02,25.4 48.64,25.4 48.13,25.91 45.47,25.91 43.94,27.43 43.94,30.73 39.24,35.43 35.94,35.43 35.31,36.07 30.86,36.07 B22.L2 | v168.66,96.65 171.07,96.65 172.85,94.87 | 172.85,94.87 178.69,89.03 179.2,89.03 185.17,83.06 189.48,83.06 191.77,80.77 193.8,80.77 194.69,79.88 199.9,79.88 204.22,75.56 204.85,75.56 216.79,63.63 220.73,63.63 241.3,43.05 242.06,43.05 v246.63,38.48 | v231.14,141.48 236.6,136.02 237.11,136.02 237.62,135.51 237.62,133.6 238.63,132.59 238.63,131.19 252.35,117.47 253.24,117.47 254.38,116.33 254.89,116.33 A05.H1 | 172.85,94.87 v172.85,94.23
  Bottom 0.152: v78.99,21.97 90.17,21.97 150.24,82.04 154.05,82.04 v168.66,96.65 | v246.63,38.48 246.63,38.73 251.84,43.94 253.24,43.94 254.89,45.59 B05.H1 | v231.14,141.48 224.16,141.48 222.12,143.51 v172.85,94.23
I_DATA04  (via drill 0.61)
  Top 0.152: v108.46,3.56 107.7,4.32 99.44,4.32 94.49,9.27 73.79,9.27 63.5,19.56 45.47,19.56 44.32,20.7 43.31,20.7 38.1,25.91 32.77,25.91 30.61,28.07 30.61,29.46 B22.N2 | v184.15,62.23 185.8,62.23 v186.18,61.85 | v249.68,113.54 251.33,113.54 251.71,113.16 A05.J1 | v244.47,49.78 244.98,49.28 244.98,48.64 250.32,43.31 251.71,43.31 B05.J1 | v224.41,24.89 224.28,24.89 v203.2,45.97 | v213.11,57.91 213.11,58.42 v200.79,70.74
  Bottom 0.152: v108.46,3.56 121.54,3.56 134.11,16.13 134.62,16.13 151.38,32.89 151.89,32.89 153.42,34.42 156.72,34.42 183.64,61.34 183.64,61.72 v184.15,62.23 | v186.18,61.85 187.2,61.85 191.52,66.17 193.68,66.17 198.88,71.37 200.79,71.37 | 200.79,71.37 209.8,80.39 212.09,80.39 226.44,94.74 229.74,94.74 241.94,106.93 243.08,106.93 v249.68,113.54 | v244.47,49.78 244.47,49.28 241.81,46.61 241.81,45.09 240.92,44.2 240.92,41.4 v224.41,24.89 | v203.2,45.97 203.2,48.01 v213.11,57.91 | 200.79,71.37 v200.79,70.74
I_DATA05  (via drill 0.61)
  Top 0.152: v165.23,6.1 165.99,5.33 162.31,1.65 124.33,1.65 123.57,2.41 122.43,2.41 122.05,2.79 108.08,2.79 106.93,3.94 99.31,3.94 94.36,8.89 73.66,8.89 63.37,19.18 45.34,19.18 44.2,20.32 43.18,20.32 40.77,22.73 35.94,22.73 35.31,23.37 30.86,23.37 B22.R2 | v182.25,14.61 182.63,14.61 v187.32,9.91 | v202.18,22.23 202.18,21.59 213.74,10.03 216.53,10.03 v217.81,8.76 | v236.22,22.23 v233.43,22.23 | v250.06,108.08 251.33,106.81 251.71,106.81 A05.L1 | v196.85,65.15 196.85,65.02 197.87,64.01 201.55,64.01 211.07,54.48 211.2,54.48 215.77,49.91 215.77,48.77 v216.92,47.62
  Bottom 0.152: v165.23,6.1 169.54,6.1 175.64,12.19 178.69,12.19 179.58,13.08 180.72,13.08 v182.25,14.61 | v187.32,9.91 189.87,9.91 v202.18,22.23 202.44,22.61 210.06,30.23 210.06,33.91 210.57,34.42 210.57,35.94 216.41,41.78 216.41,46.61 216.92,47.12 v216.92,47.62 | v217.81,8.76 219.96,8.76 v233.43,22.23 | v236.22,22.23 236.47,22.23 248.67,34.42 250.06,34.42 251.71,36.07 B05.L1 | v250.06,108.08 238.25,96.27 238.25,96.14 236.35,94.23 235.59,94.23 233.93,92.58 228.09,92.58 215.01,79.5 211.2,79.5 v196.85,65.15
I_DATA06  (via drill 0.61)
  Top 0.152: v29.08,66.17 70.99,24.26 71.63,24.26 72.01,23.88 72.9,23.88 74.04,22.73 79.38,22.73 83.31,18.8 89.53,18.8 v96.27,12.06 | v181.23,82.04 184.53,82.04 186.94,79.63 187.58,79.63 188.47,78.74 189.99,78.74 v203.2,65.53 | v232.66,91.06 233.3,91.06 v241.3,83.06 | v257.18,101.09 257.18,101.35 256.03,102.49 A05.M1 | v305.82,81.28 305.82,79.5 304.67,78.36 304.17,78.36 302.13,80.39 302.13,83.69 287.91,97.92 281.56,97.92 v267.84,111.63
  Bottom 0.152: v29.08,66.17 26.42,66.17 17.91,57.66 17.91,56.26 B23.D2 | v96.27,12.06 99.31,12.06 99.44,12.19 105.79,12.19 118.49,24.89 123.57,24.89 147.96,49.28 148.46,49.28 v181.23,82.04 | v203.2,65.53 203.58,65.53 223.27,85.22 226.82,85.22 v232.66,91.06 | v241.3,83.06 243.46,83.06 247.14,86.74 247.14,88.01 247.9,88.77 247.9,90.81 255.02,97.92 255.27,97.92 255.91,98.55 255.91,99.82 v257.18,101.09 257.56,101.35 v267.84,111.63 | v305.82,81.28 306.58,82.04 305.44,83.19 304.67,83.19 303.53,82.04 302.64,82.04 275.34,54.74 274.32,54.74 267.08,47.5 267.08,47.12 264.41,44.45 264.41,43.81 261.75,41.15 261.24,41.15 256.03,35.94 256.03,34.04 B05.M1
I_DATA07  (via drill 0.61)
  Top 0.152: v250.7,30.61 251.33,29.97 251.33,29.59 253.49,27.43 254.89,27.43 B05.P1 | v274.7,60.33 273.56,60.33 272.54,61.34 272.54,62.48 268.86,66.17 267.59,66.17 255.91,77.85 255.91,78.49 254.76,79.63 254.76,80.52 v247.9,87.38 247.52,87.63 236.73,98.42 v236.47,98.42 | v110.74,138.81 169.8,138.81 v170.31,138.3 | v172.59,138.3 172.97,138.3 176.28,135 176.78,135 180.09,131.7 180.97,131.7 204.22,108.46 209.17,108.46 211.58,106.05 211.96,106.05 219.84,98.17 220.22,98.17 v225.81,92.58
  Bottom 0.152: v250.7,30.61 250.06,30.61 249.94,30.48 249.17,30.48 248.41,31.24 249.17,32 249.56,32 263.02,45.47 263.02,49.28 265.56,51.82 266.19,51.82 266.57,52.2 266.57,52.83 269.24,55.5 269.75,55.5 274.57,60.33 v274.7,60.33 | v247.9,87.38 247.9,87.63 249.68,89.41 249.81,89.41 253.49,93.09 253.49,94.49 255.14,96.14 A05.P1 | v110.74,138.81 21.59,49.66 18.16,49.66 B23.F2 | v172.59,138.3 v170.31,138.3 | v225.81,92.58 227.58,92.58 227.97,92.96 231.01,92.96 v236.47,98.42
I_DATA08  (via drill 0.61)
  Top 0.152: v266.19,35.31 266.19,37.72 v264.29,39.62 | v273.3,48.9 273.3,50.04 261.87,61.47 261.87,61.72 257.56,66.04 257.05,66.04 v250.95,72.14 | v259.21,85.72 258.7,85.72 257.68,86.74 257.68,88.39 A05.S1 | v72.9,8.51 71.37,10.03 35.94,10.03 18.54,27.43 18.54,37.08 17.91,37.72 17.91,42.16 B23.J2 | v118.87,20.7 120.52,20.7 v123.44,17.78 | v172.47,60.45 v169.04,60.45 | v212.34,94.49 212.34,93.98 226.44,79.88 226.69,79.88 v231.9,74.68 | v235.46,77.98 236.09,77.98 v243.21,70.87
  Bottom 0.152: v266.19,35.31 259.97,29.08 259.97,27.69 256.03,23.75 256.03,21.34 B05.S1 | v264.29,39.62 264.29,39.88 v273.3,48.9 | v250.95,72.14 252.09,73.28 252.09,75.56 | 252.09,75.56 252.09,77.72 256.41,82.04 256.41,82.93 v259.21,85.72 | v72.9,8.51 106.68,8.51 v118.87,20.7 | v123.44,17.78 124.08,17.78 166.12,59.82 168.4,59.82 v169.04,60.45 | v172.47,60.45 179.96,67.94 180.59,67.94 184.4,71.75 184.91,71.75 185.29,72.14 186.31,72.14 192.79,78.61 196.47,78.61 v212.34,94.49 | v231.9,74.68 232.16,74.68 v235.46,77.98 | v243.21,70.87 247.4,70.87 252.09,75.56
I_DATA09  (via drill 0.61)
  Top 0.152: v129.03,137.03 149.99,137.03 151.76,135.25 152.02,135.25 162.94,124.33 165.74,124.33 165.99,124.08 167.13,124.08 167.39,123.83 179.71,123.83 184.78,118.75 186.44,118.75 188.59,116.59 | 188.59,116.59 194.18,111 194.18,109.6 198.37,105.41 198.37,104.9 199.52,103.76 199.52,99.95 220.34,79.12 222.25,79.12 228.98,72.39 228.98,70.99 239.14,60.83 240.54,60.83 241.68,59.69 241.68,58.29 242.32,57.66 243.71,57.66 245.36,56.01 B05.D2 | v244.22,124.46 242.32,124.46 v231.78,135 | v220.22,123.32 219.58,123.32 v208.15,134.75 | 188.59,116.59 v188.34,116.33
  Bottom 0.152: v129.03,137.03 105.79,113.79 93.09,113.79 53.09,73.79 53.09,69.72 39.24,55.88 38.61,55.88 19.68,36.96 18.16,36.96 B23.L2 | v244.22,124.46 244.73,124.97 245.36,124.97 A05.D2 | v231.78,135 231.78,134.37 221.11,123.7 220.6,123.7 v220.22,123.32 | v208.15,134.75 206.76,134.75 v188.34,116.33
I_DATA10  (via drill 0.61)
  Top 0.152: v138.43,140.08 v170.31,140.08 | v179.45,142.49 194.31,142.49 194.82,141.99 210.82,141.99 v216.28,136.53 | v222.12,142.24 232.66,142.24 250.06,124.84 250.06,123.32 249.68,122.94 A05.E2 | v244.47,58.17 246,56.64 246.63,56.64 247.14,56.13 247.14,55.37 248.79,53.72 248.79,53.09 B05.E2 | v258.83,76.07 258.83,76.2 v256.67,78.36 | v269.37,98.55 v272.16,95.76 | v267.84,98.55 267.84,99.69 248.41,119.13 247.9,119.13 v246.38,120.65
  Bottom 0.152: v138.43,140.08 80.52,82.17 78.49,82.17 78.36,82.04 67.69,82.04 42.67,57.02 42.16,57.02 17.91,32.77 17.91,30.86 B23.N2 | v170.31,140.08 177.04,140.08 v179.45,142.49 | v216.28,136.53 216.41,136.53 v222.12,142.24 | v244.47,58.17 244.47,61.21 244.86,61.59 244.86,62.36 248.67,66.17 248.92,66.17 v258.83,76.07 | v256.67,78.36 256.67,80.52 259.71,83.57 259.84,83.57 260.86,84.58 260.86,84.71 270.89,94.74 271.14,94.74 v272.16,95.76 | v267.84,98.55 v269.37,98.55 | v246.38,120.65 247.4,120.65 248.54,121.79 A05.E2
I_DATA11  (via drill 0.61)
  Top 0.152: v180.97,75.44 184.4,75.44 217.04,42.8 217.93,42.8 v231.65,29.08 | v201.04,76.33 198.63,76.33 197.99,76.96 194.18,76.96 193.93,77.22 192.02,77.22 190.12,79.12 188.59,79.12 v187.32,80.39
  Bottom 0.152: v231.65,29.08 233.93,29.08 236.09,31.24 236.73,31.24 248.67,43.18 248.67,45.21 248.79,45.34 B05.H2 | B23.R2 17.91,23.11 17.91,18.8 20.7,16 19.56,14.86 19.56,13.72 28.96,4.32 97.92,4.32 99.44,5.84 105.03,5.84 107.19,8 107.95,8 118.49,18.54 124.08,18.54 v180.97,75.44 181.36,75.69 184.66,78.99 185.93,78.99 v187.32,80.39 | v201.04,76.33 204.6,79.88 208.53,79.88 225.68,97.03 227.97,97.03 236.47,105.54 236.47,105.66 246.25,115.44 248.54,115.44 A05.H2
I_DATAIN  (via drill 0.61)
  Top 0.152: v108.58,5.08 94.11,19.56 83.57,19.56 81.41,21.72 81.41,23.11 B18.R2 | v183.64,72.77 186.44,72.77 190.75,68.45 190.75,68.2 v217.3,41.66 | v233.68,58.67 233.81,58.67 248.16,44.32 248.28,44.32 251.84,40.77 252.86,40.77 258.19,35.43 259.59,35.43 261.24,33.78 B04.M2 | v233.17,120.9 243.46,110.62 249.81,110.62 253.24,107.19 254.38,107.19 258.95,102.62 259.08,102.62 260.1,101.6 261.24,102.74 A04.M2 | v185.55,79.76 185.55,76.83 v186.56,75.82
  Bottom 0.152: v108.58,5.08 115.44,5.08 142.88,32.51 143.38,32.51 v183.64,72.77 183.9,73.15 v186.56,75.82 | v217.3,41.66 217.3,42.29 218.19,43.18 218.19,43.81 223.14,48.77 223.77,48.77 v233.68,58.67 | v233.17,120.9 232.16,120.9 224.66,113.41 222.88,113.41 221.74,112.27 221.74,112.14 221.23,111.63 220.6,111.63 219.96,111 219.96,109.86 213.36,103.25 212.85,103.25 208.53,98.93 205.23,98.93 199.77,93.47 199.26,93.47 v185.55,79.76
I_EXTA0  (via drill 0.61)
  Top 0.152: v250.44,17.91 249.81,17.91 243.59,24.13 243.59,24.64 239.78,28.45 v239.78,28.57 | v254.89,50.04 v239.9,65.02 | v248.54,77.34 248.54,78.23 246.51,80.26 A05.V2 | v99.69,46.1 101.47,46.1 102.62,44.96 106.93,44.96 107.7,44.2 109.73,44.2 121.67,32.26 131.32,32.26 139.19,24.38 139.19,21.08 150.24,10.03 162.43,10.03 v170.69,1.78 | v196.85,6.35 198.75,6.35 200.15,4.95 203.2,4.95 v204.85,3.3
  Bottom 0.152: v250.44,17.91 246.51,13.97 246.51,11.81 B05.V2 | v254.89,50.04 252.22,47.37 252.22,45.72 237.24,30.73 239.4,28.57 v239.78,28.57 239.52,28.19 236.22,24.89 232.79,24.89 211.2,3.3 v204.85,3.3 | v239.9,65.02 239.9,68.71 v248.54,77.34 | v99.69,46.1 92.84,39.24 92.33,39.24 71.75,18.67 68.71,21.72 68.71,23.11 B19.R2 | v170.69,1.78 192.28,1.78 v196.85,6.35
I_EXTA1  (via drill 0.61)
  Top 0.152: v243.21,22.23 245.62,19.81 245.62,18.16 B05.T2 | v224.92,4.06 224.16,4.06 221.74,6.48 221.23,6.48 218.19,9.53 217.55,9.53 v211.2,15.88 | v196.47,8.76 194.94,8.76 v190.25,13.46 | v196.85,19.68 196.85,19.94 v194.18,22.61 | v199.64,29.84 v199.64,35.43 | v246.76,85.22 246.76,86.36 246.51,86.61 A05.T2 | v120.52,4.32 108.2,4.32 102.49,10.03 99.44,10.03 90.3,19.18 83.44,19.18 72.9,29.72 68.96,29.72 B19.N2 | v128.14,11.43 129.79,11.43 131.19,10.03 135.25,10.03 137.16,8.13 140.08,8.13 140.46,7.75 153.29,7.75 155.19,5.84 162.81,5.84 v164.08,4.57 | v176.91,9.27 178.82,9.27 v182.12,5.97
  Bottom 0.152: v243.21,22.23 242.82,22.23 232.28,11.68 232.28,11.43 v224.92,4.06 | v211.2,15.88 208.41,15.88 206.88,14.35 206.5,14.35 205.36,13.21 202.06,13.21 201.04,12.19 199.9,12.19 v196.47,8.76 | v196.85,19.68 196.34,19.18 196.34,16.89 192.02,12.57 191.13,13.46 v190.25,13.46 189.87,13.72 v182.12,5.97 | v194.18,22.61 194.18,24.38 v199.64,29.84 | v199.64,35.43 199.64,36.2 219.84,56.39 219.84,56.64 228.85,65.66 228.85,65.91 244.6,81.66 244.6,83.06 v246.76,85.22 | v120.52,4.32 121.03,4.32 v128.14,11.43 | v164.08,4.57 172.21,4.57 v176.91,9.27
I_EXTA2  (via drill 0.61)
  Top 0.152: v116.84,74.04 121.67,74.04 v136.78,58.93 | v162.94,85.09 163.19,85.09 180.34,67.94 181.23,67.94 v189.36,59.82 | v229.11,89.28 229.74,89.28 232.79,86.23 236.09,86.23 240.79,81.53 240.79,81.03 v247.14,74.68 | v255.65,82.42 251.33,86.74 251.33,88.14 249.68,89.79 A05.S2 | v251.33,19.05 250.19,20.19 249.94,20.19 B05.S2 | v253.24,20.95 253.11,20.95 215.39,58.67 214,58.67 201.17,71.5 200.28,71.5 199.9,71.12 200.03,70.99 200.03,70.36 v203.2,67.18
  Bottom 0.152: v116.84,74.04 80.39,37.59 74.04,37.59 73.41,36.96 68.96,36.96 B19.L2 | v136.78,58.93 137.29,58.93 161.8,83.44 161.8,83.95 v162.94,85.09 | v189.36,59.82 191.01,59.82 194.56,63.37 199.39,63.37 v203.2,67.18 224.28,88.27 226.31,88.27 226.44,88.39 228.22,88.39 v229.11,89.28 | v247.14,74.68 247.9,74.68 v255.65,82.42 | v253.24,20.95 v251.33,19.05
I_INIT  (via drill 0.61)
  Top 0.152: v294.39,82.3 295.27,82.3 296.16,81.41 A01.V2 | A04.V2 259.21,80.26 259.21,78.49 265.05,72.64 265.43,72.64 274.07,64.01 274.57,64.01 v275.34,63.25 275.59,62.87 275.59,62.48 277.24,60.83 277.5,60.83 v278,60.33 | B06.N1 239.01,29.72 239.01,28.19 255.65,11.56 258.06,11.56 B04.V2 259.46,10.67 264.03,6.1 v265.81,6.1 | v275.97,56.52 275.97,55.24 284.23,46.99 284.23,44.45 291.59,37.08 291.59,31.88 293.62,29.84 293.62,28.7 294.77,27.56 294.77,24.77 294.89,24.64 294.89,23.75 296.8,21.84 296.8,19.18 297.94,18.03 297.94,12.45 297.31,11.81 B01.V2
  Bottom 0.152: v275.34,63.25 v294.39,82.3 | v265.81,6.1 269.75,10.03 291.08,10.03 291.72,10.67 296.16,10.67 B01.V2 | v278,60.33 277.62,60.33 275.97,58.67 v275.97,56.52
I_IOP1  (via drill 0.61)
  Top 0.152: v251.33,73.66 252.86,73.66 v258.32,68.2 | v268.73,78.49 269.24,78.49 v274.45,73.28 301.12,46.61 301.12,41.02 300.48,40.39 B01.K2 | v301.24,107.82 300.48,108.58 300.48,108.84 A01.K2
  Bottom 0.152: v251.33,73.66 243.46,65.79 243.46,65.66 B06.A1 | v258.32,68.2 258.44,68.2 v268.73,78.49 | v301.24,107.82 301.24,107.57 298.83,105.16 298.83,97.79 297.81,96.77 297.18,96.77 284.61,84.2 284.61,83.44 v274.45,73.28
I_IOP2  (via drill 0.61)
  Top 0.152: v242.7,54.1 241.68,55.12 240.41,55.12 B06.D1 | v294.77,106.81 296.29,105.28 297.69,105.28 299.34,103.63 A01.M2 | v302.89,34.92 302.89,35.18 302.13,35.94 302.13,47.88 v268.99,81.03
  Bottom 0.152: v242.7,54.1 242.7,54.74 v268.99,81.03 v294.77,106.81 | v302.89,34.92 301.75,33.78 300.74,33.78 B01.M2
I_IOP4  (via drill 0.61)
  Top 0.152: v288.54,19.56 286.51,19.56 272.03,34.04 271.78,34.04 266.32,39.5 266.06,39.5 257.43,48.13 256.41,48.13 256.29,48.26 255.52,48.26 v251.71,52.07 251.46,52.45 249.94,53.98 v249.81,53.98 | v245.49,45.85 244.73,45.85 243.46,47.12 242.44,47.12 240.41,49.15 B06.F1 | v285.75,83.69 285.62,83.69 v282.57,86.74
  Bottom 0.152: v288.54,19.56 295.53,26.54 299.34,26.54 B01.P2 | v245.49,45.85 v251.71,52.07 | v285.75,83.69 286.26,84.2 286.26,84.71 297.56,96.01 298.07,96.01 298.45,96.39 299.34,96.39 A01.P2 | v282.57,86.74 281.94,86.74 251.33,56.13 251.33,55.5 v249.81,53.98
I_IRQ  (via drill 0.61)
  Top 0.152: v87.25,50.8 87.63,50.8 v128.78,9.65 | v155.07,31.11 155.07,30.61 156.59,29.08 159.38,29.08 160.15,28.32 161.04,28.32 172.72,16.64 173.99,16.64 179.45,11.18 179.83,11.18 181.74,9.27 183.9,9.27 v190.12,3.05 | v201.93,7.11 203.96,7.11 v205.1,5.97 | v219.07,18.67 222.5,18.67 v238.89,2.29 | v276.48,104.27 276.48,105.41 269.49,112.39 268.99,112.39 v259.08,122.3 | v259.97,123.83 259.97,125.86 249.81,136.02 248.79,136.02 v242.82,141.99 | v211.2,125.09 v217.68,118.62 | v188.72,103.5 188.59,103.5 184.53,107.57 183.51,107.57 183.26,107.82 182.75,107.82 170.43,120.14 v159.38,120.14
  Bottom 0.152: v128.78,9.65 128.78,10.29 134.24,15.75 134.75,15.75 147.07,28.07 152.02,28.07 v155.07,31.11 | v190.12,3.05 192.41,3.05 196.47,7.11 v201.93,7.11 | v205.1,5.97 205.87,5.97 214.63,14.73 215.14,14.73 v219.07,18.67 | v238.89,2.29 240.28,2.29 243.08,5.08 243.71,5.08 249.94,11.3 249.94,11.81 258.83,20.7 259.59,20.7 259.97,21.08 260.73,21.08 270.89,31.24 272.29,31.24 273.94,32.89 B03.M2 | B18.F2 81.66,49.66 86.11,49.66 v87.25,50.8 87.5,51.18 87.5,53.21 91.69,57.4 92.96,57.4 136.02,100.46 136.4,100.46 156.08,120.14 v159.38,120.14 | v276.48,104.27 275.84,103.63 275.34,103.63 A03.M2 | v259.08,122.3 259.08,122.94 v259.97,123.83 | v242.82,141.99 241.05,141.99 v217.68,118.62 | v211.2,125.09 210.31,125.09 v188.72,103.5
I_LINE  (via drill 0.61)
  Top 0.152: v105.79,19.05 105.28,19.56 96.27,19.56 81.41,34.42 81.41,35.81 B18.L2 | v116.08,23.62 117.6,23.62 118.49,22.73 122.81,22.73 129.79,15.75 130.05,15.75 132.97,12.83 134.75,12.83 137.54,10.03 140.59,10.03 142.49,8.13 v163.19,8.13 | v200.03,40.01 200.03,39.75 204.34,35.43 204.34,35.31 204.72,34.92 205.61,34.92 214.12,26.42 v214.25,26.42 | B03.V2 271.14,10.41 271.53,10.03 263.14,1.65 262.89,1.65 262.64,1.91 247.78,1.91 247.4,2.29 246.13,2.29 244.86,3.56 243.08,3.56 230.63,16 226.31,16 215.39,26.92 v215.39,27.56 215.39,27.94 214.76,28.57 215.39,29.21 215.39,30.73 213.61,32.51 v213.61,33.15 | v266.57,82.3 269.37,82.3 270.26,81.41 270.76,81.41 A03.V2
  Bottom 0.152: v105.79,19.05 111.51,19.05 v116.08,23.62 | v163.19,8.13 165.23,8.13 169.29,12.19 172.59,12.19 199.52,39.12 199.52,39.5 v200.03,40.01 | v215.39,27.56 v214.25,26.42 | v266.57,82.3 264.8,82.3 264.03,81.53 264.03,81.15 262,79.12 259.59,79.12 236.85,56.39 236.85,55.75 222.88,41.78 222.25,41.78 v213.61,33.15
I_MB00  (via drill 0.61)
  Top 0.152: v232.66,123.44 v234.95,123.44 | v241.3,129.79 241.3,129.92 240.16,131.06 A06.B1 | v300.99,71.12 300.99,78.99 v297.43,82.55 | v302.64,90.68 302.64,92.58 302.13,93.09 302.13,97.66 v300.1,99.69 | v304.29,111 304.29,114.43 299.85,118.87 299.85,120.78 292.61,128.02 292.61,129.41 290.96,131.06 A02.B1 289.81,132.21 288.16,133.86 286.77,133.86 278.89,141.73 v254.38,141.73
  Bottom 0.152: v232.66,123.44 231.27,122.05 231.27,121.67 225.93,116.33 224.54,116.33 A07.H2 | v234.95,123.44 v241.3,129.79 241.68,130.05 242.7,130.05 v254.38,141.73 | v300.99,71.12 294.77,64.9 294.77,64.52 292.61,62.36 291.21,62.36 B02.B1 | v297.43,82.55 297.43,85.47 v302.64,90.68 | v300.1,99.69 300.1,101.6 304.29,105.79 v304.29,111
I_MB01  (via drill 0.61)
  Top 0.152: v288.8,57.78 290.07,56.52 290.07,56.26 B02.D1 | v291.72,64.26 291.72,65.66 290.83,66.55 290.32,66.55 280.29,76.58 280.29,76.83 260.86,96.27 260.86,97.28 v260.22,97.92 259.84,98.17 259.08,98.93 258.06,98.93 248.67,108.33 v248.16,108.33 | v250.19,111.76 246.76,115.19 246.76,117.22 246,117.98 245.49,117.98 240.16,123.32 240.16,124.71 A06.D1
  Bottom 0.152: A07.N2 221.11,100.71 221.11,103.25 230.89,113.03 231.52,113.03 238.25,119.76 238.25,123.7 239.27,124.71 A06.D1 | v288.8,57.78 288.8,60.2 288.93,60.33 288.93,61.98 289.94,62.99 290.45,62.99 v291.72,64.26 | v260.22,97.92 260.22,98.04 266.19,104.01 266.45,104.01 272.29,109.86 272.8,109.86 283.46,120.52 283.97,120.52 286.77,123.32 288.16,123.32 289.81,124.97 A02.D1 | v250.19,111.76 249.81,111.76 248.16,110.11 v248.16,108.33
I_MB02  (via drill 0.61)
  Top 0.152: v296.55,58.8 295.91,58.8 290.96,63.75 290.96,64.14 289.69,65.41 289.69,66.04 268.99,86.74 268.61,86.74 v267.84,87.5 267.46,87.25 266.45,86.23 264.54,86.23 v234.06,116.71 | v297.31,116.97 295.78,118.49 295.78,119.89 294.13,121.54 A02.E1 | v215.9,95.38 223.39,87.88 223.39,84.84 A07.U2 | v273.56,93.22 268.61,98.17 268.61,98.93 268.22,99.31 268.22,99.95 246.38,121.79 243.59,121.79 A06.E1
  Bottom 0.152: v296.55,58.8 294.13,56.39 294.13,53.09 B02.E1 | v297.31,116.97 v273.56,93.22 v267.84,87.5 | v215.9,95.38 215.9,98.55 v234.06,116.71
I_MB03  (via drill 0.61)
  Top 0.152: v220.09,95.89 217.04,98.93 213.74,98.93 213.11,99.57 208.66,99.57 A08.N2 | v285.75,52.2 290.07,47.88 290.07,43.56 B02.J1 | v306.58,73.79 306.58,82.3 305.31,83.57 305.31,94.74 305.18,94.87 305.18,95.25 v303.53,96.9 | v306.58,100.08 v292.61,114.05 292.23,114.3 267.84,138.68 v267.59,138.68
